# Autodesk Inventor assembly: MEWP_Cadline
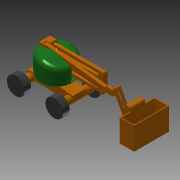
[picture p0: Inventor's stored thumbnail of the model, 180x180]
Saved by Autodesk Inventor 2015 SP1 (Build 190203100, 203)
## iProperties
Created: 2014-09
Part Number: MEWP_Cadline
Document SubType Name: Assembly
Designer: liam.oconnor
Author: liam.oconnor
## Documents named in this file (25)
- C:\Users\liam.oconnor\Documents\Cadline - Liam info\Blogg - White Papers\Inventor  MEWP\MEWP_Cadline.iam
- C:\Users\liam.oconnor\Documents\Cadline - Liam info\Blogg - White Papers\Inventor  MEWP\Wheel Base.ipt
- Wheel Base.ipt
- C:\Users\liam.oconnor\Documents\Cadline - Liam info\Blogg - White Papers\Inventor  MEWP\Main Body.ipt
- Main Body.ipt
- C:\Users\liam.oconnor\Documents\Cadline - Liam info\Blogg - White Papers\Inventor  MEWP\Bottom Arm.ipt
- Bottom Arm.ipt
- C:\Users\liam.oconnor\Documents\Cadline - Liam info\Blogg - White Papers\Inventor  MEWP\Joint 1.ipt
- Joint 1.ipt
- C:\Users\liam.oconnor\Documents\Cadline - Liam info\Blogg - White Papers\Inventor  MEWP\Joint 2.ipt
- Joint 2.ipt
- C:\Users\liam.oconnor\Documents\Cadline - Liam info\Blogg - White Papers\Inventor  MEWP\Upper Arm_P1.ipt
- Upper Arm_P1.ipt
- C:\Users\liam.oconnor\Documents\Cadline - Liam info\Blogg - White Papers\Inventor  MEWP\Upper Arm_P3.ipt
- Upper Arm_P3.ipt
- C:\Users\liam.oconnor\Documents\Cadline - Liam info\Blogg - White Papers\Inventor  MEWP\Upper Arm_P2.ipt
- Upper Arm_P2.ipt
- C:\Users\liam.oconnor\Documents\Cadline - Liam info\Blogg - White Papers\Inventor  MEWP\Upper Arm_P4.ipt
- Upper Arm_P4.ipt
- C:\Users\liam.oconnor\Documents\Cadline - Liam info\Blogg - White Papers\Inventor  MEWP\Arm_3.ipt
- Arm_3.ipt
- C:\Users\liam.oconnor\Documents\Cadline - Liam info\Blogg - White Papers\Inventor  MEWP\Basket Pivot Joint.ipt
- Basket Pivot Joint.ipt
- C:\Users\liam.oconnor\Documents\Cadline - Liam info\Blogg - White Papers\Inventor  MEWP\Basket.ipt
- Basket.ipt
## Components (13 placed, 12 different names)
1. Wheel Base:1 — Mate:1, Mate:2, Mate:3, Body_Base_Rotation
2. Main Body:1 — Mate:2, Mate:3, Mate:4, BaseAngle1, Mate:9, Angle:4, Angle:6, Angle:9
3. Bottom Arm:1 — Mate:4, BaseAngle1, Mate:5, Mate:6, Mate:9
4. Joint 1:1 — Mate:5, Mate:6, Mate:7, Angle:3, Angle:4, Mate:11
5. Bottom Arm:2 — Mate:7, Angle:3, Mate:10, Mate:11, Mate:12, Mate:13
6. Joint 2:1 — Mate:10, Mate:12, Mate:13, Body_Base_Rotation, Angle:6, Mate:14, Mate:15, Upper_Arm_Angle
7. Upper Arm_P1:1 — Mate:14, Mate:15, Upper_Arm_Angle, Flush:1, Flush:2, Mate:16, Mate:17, Mate:18, Mate:19
8. Upper Arm_P3:1 — Flush:1, Flush:2, Mate:16, Mate:21, Mate:22
9. Upper Arm_P4:1 — Mate:17, Mate:18, Mate:19, Mate:20
10. Upper Arm_P2:1 — Mate:20, Mate:21, Mate:22, Mate:23, Mate:24, Angle:8
11. Arm_3:1 — Mate:23, Mate:24, Angle:8, Mate:25, Mate:26
12. Basket Pivot Joint:1 — Mate:25, Mate:26, Mate:27, Mate:28, Angle:9, Angle:10
13. Basket:1 — Mate:27, Mate:28, Angle:10
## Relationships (38: Mate 27, Angle 9, Flush 2)
- Body_Base_Rotation [Angle]: Wheel Base:1 ↔ Joint 2:1
- BaseAngle1 [Angle]: Main Body:1 ↔ Bottom Arm:1
- Upper_Arm_Angle [Angle]: Joint 2:1 ↔ Upper Arm_P1:1
- Angle:3: Joint 1:1 ↔ Bottom Arm:2
- Angle:6: Main Body:1 ↔ Joint 2:1
- Angle:4: Main Body:1 ↔ Joint 1:1
- Angle:8: Upper Arm_P2:1 ↔ Arm_3:1
- Angle:9: Main Body:1 ↔ Basket Pivot Joint:1
- Angle:10: Basket Pivot Joint:1 ↔ Basket:1
- Mate:1: Wheel Base:1
- Mate:2: Wheel Base:1 ↔ Main Body:1
- Mate:3: Wheel Base:1 ↔ Main Body:1
- Mate:4: Main Body:1 ↔ Bottom Arm:1
- Mate:5: Bottom Arm:1 ↔ Joint 1:1
- Mate:6: Bottom Arm:1 ↔ Joint 1:1
- Mate:7: Joint 1:1 ↔ Bottom Arm:2
- Mate:9: Main Body:1 ↔ Bottom Arm:1
- Mate:10: Bottom Arm:2 ↔ Joint 2:1
- Mate:11: Joint 1:1 ↔ Bottom Arm:2
- Mate:12: Bottom Arm:2 ↔ Joint 2:1
- Mate:13: Bottom Arm:2 ↔ Joint 2:1
- Mate:14: Joint 2:1 ↔ Upper Arm_P1:1
- Mate:15: Joint 2:1 ↔ Upper Arm_P1:1
- Flush:1: Upper Arm_P1:1 ↔ Upper Arm_P3:1
- Flush:2: Upper Arm_P1:1 ↔ Upper Arm_P3:1
- Mate:16: Upper Arm_P1:1 ↔ Upper Arm_P3:1
- Mate:17: Upper Arm_P1:1 ↔ Upper Arm_P4:1
- Mate:18: Upper Arm_P1:1 ↔ Upper Arm_P4:1
- Mate:19: Upper Arm_P1:1 ↔ Upper Arm_P4:1
- Mate:20: Upper Arm_P4:1 ↔ Upper Arm_P2:1
- Mate:21: Upper Arm_P3:1 ↔ Upper Arm_P2:1
- Mate:22: Upper Arm_P3:1 ↔ Upper Arm_P2:1
- Mate:23: Upper Arm_P2:1 ↔ Arm_3:1
- Mate:24: Upper Arm_P2:1 ↔ Arm_3:1
- Mate:25: Arm_3:1 ↔ Basket Pivot Joint:1
- Mate:26: Arm_3:1 ↔ Basket Pivot Joint:1
- Mate:27: Basket Pivot Joint:1 ↔ Basket:1
- Mate:28: Basket Pivot Joint:1 ↔ Basket:1
## Named parameters: Base_Rotation = 0, BaseAngle1 = 0, Angle_Of_Bucket = -45 deg
